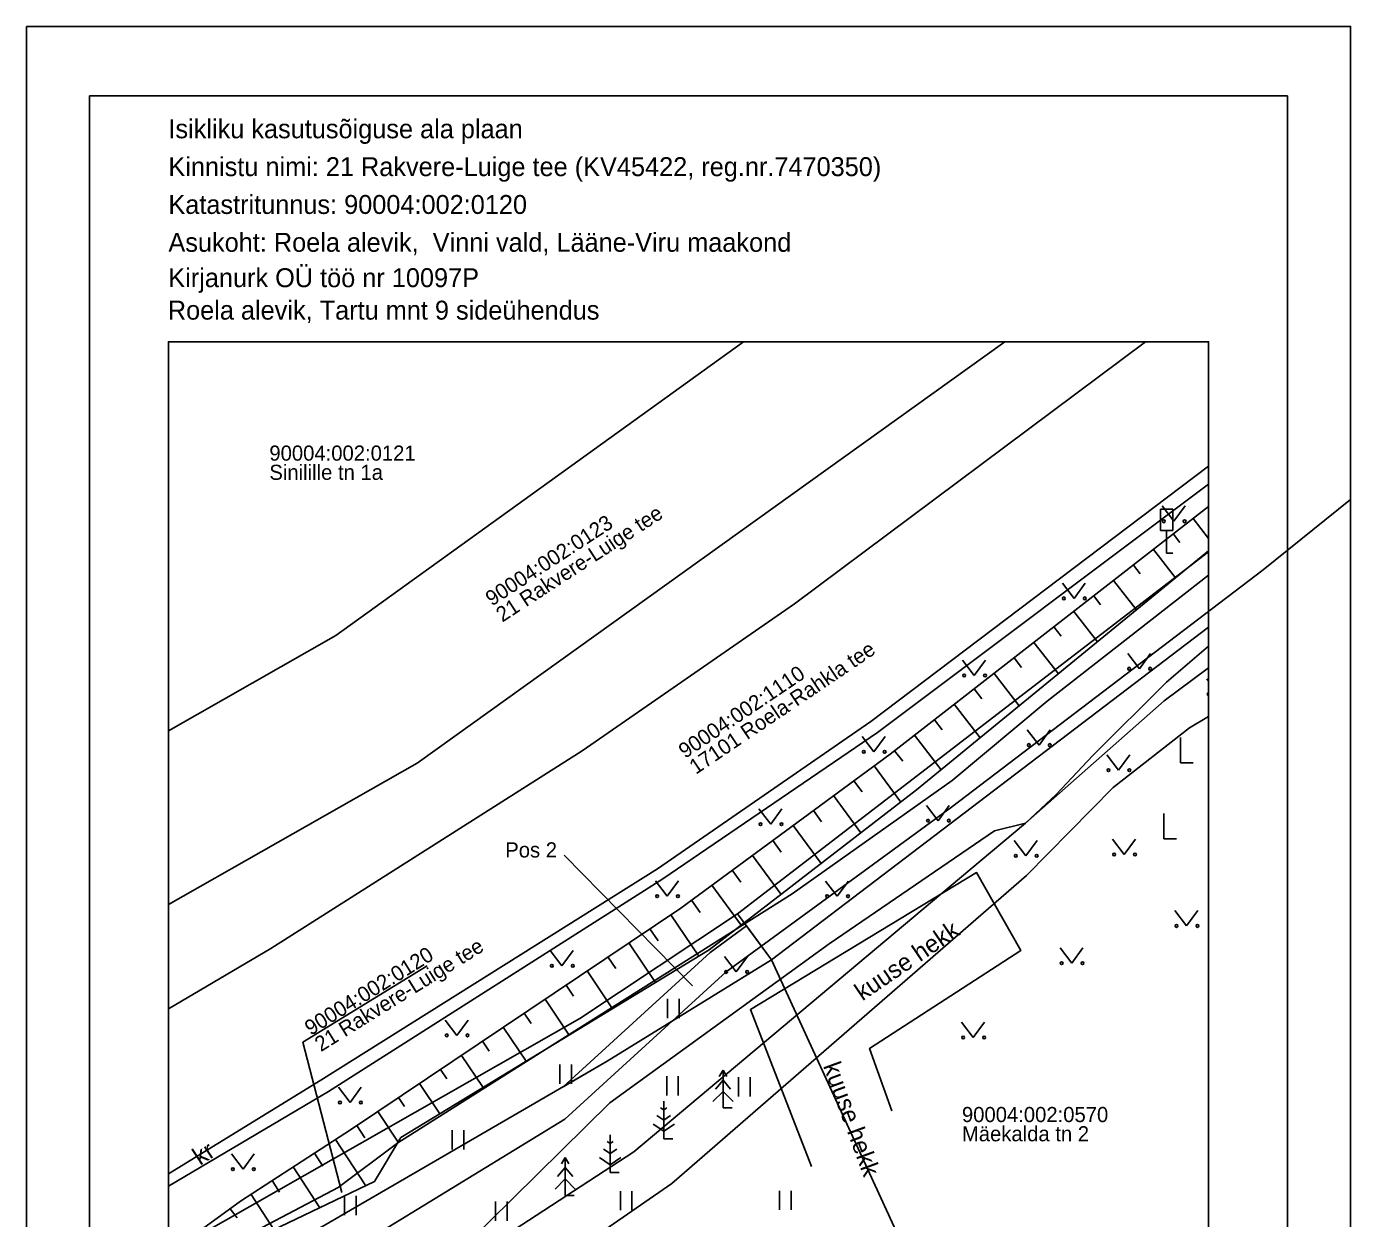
# Model space of a CAD drawing. Extents: x 647901 to 648048, y 6561291 to 6561412.
# Drawn here: x 647995.6 to 648048.1, y 6561364.9 to 6561412.2 of the extents above; entities that cross this region are included whole.
import ezdxf

# ---------------------------------------------------------------- set-up
doc = ezdxf.new("R2010")
doc.units = 0
for name, color, linetype in [('HALJASTUS', 7, 'Continuous'), ('KASUTUSALA', 7, 'Continuous'), ('LIIKLUS', 7, 'Continuous'), ('PIIR', 7, 'Continuous'), ('PR_SIDE', 7, 'Continuous'), ('PUU', 7, 'Continuous'), ('RELJEEF', 7, 'Continuous'), ('SITRASS', 7, 'Continuous'), ('TEE', 7, 'Continuous'), ('VORMISTUS_1', 7, 'Continuous')]:
    doc.layers.add(name, color=color, linetype=linetype)

msp = doc.modelspace()

# ---------------------------------------------------------------- linework, layer by layer
at = {"layer": 'HALJASTUS'}
for p, q in [((648040.646, 6561393.157), (648041.11, 6561392.55)), ((648041.11, 6561392.55), (648041.555, 6561393.157)), ((648036.689, 6561390.101), (648037.153, 6561389.494)), ((648037.153, 6561389.494), (648037.598, 6561390.101)), ((648032.732, 6561387.044), (648033.196, 6561386.438)), ((648033.196, 6561386.438), (648033.641, 6561387.044)), ((648039.279, 6561387.311), (648039.742, 6561386.705)), ((648039.742, 6561386.705), (648040.188, 6561387.311)), ((648042.423, 6561386.301), (648042.49, 6561386.213)), ((648028.752, 6561384.019), (648029.215, 6561383.412)), ((648029.215, 6561383.412), (648029.661, 6561384.019)), ((648035.299, 6561384.285), (648035.763, 6561383.679)), ((648035.763, 6561383.679), (648036.208, 6561384.285)), ((648041.376, 6561383.971), (648041.376, 6561382.971)), ((648038.454, 6561383.287), (648038.918, 6561382.68)), ((648038.918, 6561382.68), (648039.363, 6561383.287)), ((648041.376, 6561382.971), (648041.876, 6561382.971)), ((648031.298, 6561381.287), (648031.762, 6561380.68)), ((648031.762, 6561380.68), (648032.207, 6561381.287)), ((648024.66, 6561381.145), (648025.124, 6561380.539)), ((648025.124, 6561380.539), (648025.569, 6561381.145)), ((648040.717, 6561380.958), (648040.717, 6561379.958)), ((648034.78, 6561379.896), (648035.243, 6561379.29)), ((648035.243, 6561379.29), (648035.689, 6561379.896)), ((648038.678, 6561379.944), (648039.142, 6561379.338)), ((648039.142, 6561379.338), (648039.587, 6561379.944)), ((648040.717, 6561379.958), (648041.217, 6561379.958)), ((648020.556, 6561378.29), (648021.02, 6561377.683)), ((648021.02, 6561377.683), (648021.465, 6561378.29)), ((648027.297, 6561378.288), (648027.761, 6561377.681)), ((648027.761, 6561377.681), (648028.206, 6561378.288)), ((648041.153, 6561377.112), (648041.616, 6561376.505)), ((648041.616, 6561376.505), (648042.062, 6561377.112)), ((648016.385, 6561375.533), (648016.849, 6561374.926)), ((648016.849, 6561374.926), (648017.294, 6561375.533)), ((648036.598, 6561375.636), (648037.062, 6561375.029)), ((648037.062, 6561375.029), (648037.507, 6561375.636)), ((648023.297, 6561375.289), (648023.76, 6561374.682)), ((648023.76, 6561374.682), (648024.205, 6561375.289)), ((648021.036, 6561373.613), (648021.036, 6561372.852)), ((648021.491, 6561373.613), (648021.491, 6561372.852)), ((648012.214, 6561372.776), (648012.678, 6561372.169)), ((648012.678, 6561372.169), (648013.123, 6561372.776)), ((648032.694, 6561372.691), (648033.157, 6561372.084)), ((648033.157, 6561372.084), (648033.603, 6561372.691)), ((648016.767, 6561371.009), (648016.767, 6561370.248)), ((648017.223, 6561371.009), (648017.223, 6561370.248)), ((648021.007, 6561370.547), (648021.007, 6561369.785)), ((648021.462, 6561370.547), (648021.462, 6561369.785)), ((648023.853, 6561370.504), (648023.853, 6561369.742)), ((648024.308, 6561370.504), (648024.308, 6561369.742)), ((648007.983, 6561370.112), (648008.446, 6561369.505)), ((648008.446, 6561369.505), (648008.892, 6561370.112)), ((648012.499, 6561368.406), (648012.499, 6561367.645)), ((648012.954, 6561368.406), (648012.954, 6561367.645)), ((648003.738, 6561367.47), (648004.201, 6561366.864)), ((648004.201, 6561366.864), (648004.647, 6561367.47)), ((648025.476, 6561366.005), (648025.476, 6561365.244)), ((648025.931, 6561366.005), (648025.931, 6561365.244)), ((648008.23, 6561365.802), (648008.23, 6561365.041)), ((648008.685, 6561365.802), (648008.685, 6561365.041)), ((648014.217, 6561365.576), (648014.217, 6561364.815)), ((648014.672, 6561365.576), (648014.672, 6561364.815)), ((648019.165, 6561365.995), (648019.165, 6561365.234)), ((648019.62, 6561365.995), (648019.62, 6561365.234))]:
    msp.add_line(p, q, dxfattribs=at)
msp.add_lwpolyline([(648026.747, 6561366.971), (648024.322, 6561373.193), (648033.287, 6561378.621), (648035.039, 6561375.527), (648029.048, 6561371.649), (648029.933, 6561369.17)], dxfattribs=at)
for centre in [(648040.709, 6561392.55), (648041.538, 6561392.55), (648036.752, 6561389.494), (648037.58, 6561389.494), (648032.795, 6561386.438), (648033.623, 6561386.438), (648039.341, 6561386.705), (648040.17, 6561386.705), (648028.814, 6561383.412), (648029.643, 6561383.412), (648035.362, 6561383.679), (648036.191, 6561383.679), (648038.516, 6561382.68), (648039.345, 6561382.68), (648031.361, 6561380.68), (648032.19, 6561380.68), (648024.723, 6561380.539), (648025.552, 6561380.539), (648034.842, 6561379.29), (648035.671, 6561379.29), (648038.741, 6561379.338), (648039.57, 6561379.338), (648020.619, 6561377.683), (648021.447, 6561377.683), (648027.36, 6561377.681), (648028.189, 6561377.681), (648041.215, 6561376.505), (648042.044, 6561376.505), (648016.448, 6561374.926), (648017.276, 6561374.926), (648036.661, 6561375.029), (648037.489, 6561375.029), (648023.359, 6561374.682), (648024.188, 6561374.682), (648012.277, 6561372.169), (648013.105, 6561372.169), (648032.756, 6561372.084), (648033.585, 6561372.084), (648008.045, 6561369.505), (648008.874, 6561369.505), (648003.8, 6561366.864), (648004.629, 6561366.864)]:
    msp.add_circle(centre, 0.055, dxfattribs=at)
msp.add_arc((648042.485, 6561385.694), 0.055, 84.6333, 275.3667, dxfattribs=at)
at = {"layer": 'KASUTUSALA'}
msp.add_lwpolyline([(648016.894, 6561370.128), (648022.724, 6561375.457), (648024.162, 6561376.509), (648025.15, 6561375.16), (648018.64, 6561371.14)], close=True, dxfattribs=at)
at = {"layer": 'LIIKLUS'}
for p, q in [((648040.575, 6561393.037), (648040.575, 6561392.187)), ((648041.075, 6561393.037), (648040.575, 6561393.037)), ((648041.075, 6561393.037), (648041.075, 6561392.187)), ((648041.075, 6561392.187), (648040.575, 6561392.187)), ((648040.825, 6561392.187), (648040.825, 6561391.287)), ((648041.075, 6561391.287), (648040.825, 6561391.287))]:
    msp.add_line(p, q, dxfattribs=at)
at = {"layer": 'PIIR'}
for points in [[(648001.24, 6561384.247), (648007.88, 6561388.02), (648024.045, 6561399.668)], [(648024.045, 6561399.668), (648007.88, 6561388.02), (648001.24, 6561384.247)], [(648001.24, 6561377.35), (648011.11, 6561382.96), (648034.41, 6561399.668)], [(648034.41, 6561399.668), (648011.11, 6561382.96), (648001.24, 6561377.35)], [(648042.49, 6561391.337), (648023.81, 6561376.99), (648017.56, 6561372.83), (648001.24, 6561363.546)], [(648038.018, 6561347.168), (648025.15, 6561375.16), (648042.49, 6561388.346)], [(648001.24, 6561363.546), (648017.56, 6561372.83), (648023.81, 6561376.99), (648025.15, 6561375.16), (648018.64, 6561371.14), (648001.24, 6561361.053)], [(648001.24, 6561361.053), (648018.64, 6561371.14), (648025.15, 6561375.16), (648038.018, 6561347.168)], [(648011.5, 6561374.931), (648006.577, 6561371.897), (648008.122, 6561365.939)]]:
    msp.add_lwpolyline(points, dxfattribs=at)
at = {"layer": 'PR_SIDE'}
msp.add_lwpolyline([(648048.115, 6561393.411), (648044.656, 6561390.621), (648032.291, 6561381.218), (648023.359, 6561374.682), (648016.966, 6561368.839), (647995.615, 6561355.782)], dxfattribs=at)
at = {"layer": 'PUU'}
for p, q in [((648023.235, 6561370.791), (648023.085, 6561370.541)), ((648023.385, 6561370.541), (648023.235, 6561370.791)), ((648023.235, 6561370.791), (648023.235, 6561369.291)), ((648023.235, 6561370.391), (648022.935, 6561370.041)), ((648023.535, 6561370.041), (648023.235, 6561370.391)), ((648023.235, 6561369.941), (648022.835, 6561369.541)), ((648023.635, 6561369.541), (648023.235, 6561369.941)), ((648020.882, 6561369.212), (648020.758, 6561369.295)), ((648020.882, 6561369.562), (648020.882, 6561368.062)), ((648021.007, 6561369.295), (648020.882, 6561369.212)), ((648023.595, 6561369.291), (648023.235, 6561369.291)), ((648020.458, 6561368.652), (648020.882, 6561368.369)), ((648020.882, 6561368.812), (648020.615, 6561368.99)), ((648021.149, 6561368.99), (648020.882, 6561368.812)), ((648020.882, 6561368.369), (648021.306, 6561368.652)), ((648018.76, 6561368.23), (648018.76, 6561366.73)), ((648018.76, 6561367.48), (648018.493, 6561367.658)), ((648018.76, 6561367.88), (648018.635, 6561367.963)), ((648018.884, 6561367.963), (648018.76, 6561367.88)), ((648019.026, 6561367.658), (648018.76, 6561367.48)), ((648021.242, 6561368.062), (648020.882, 6561368.062)), ((648016.975, 6561367.325), (648016.825, 6561367.075)), ((648017.125, 6561367.075), (648016.975, 6561367.325)), ((648016.975, 6561367.325), (648016.975, 6561365.825)), ((648018.335, 6561367.319), (648018.76, 6561367.037)), ((648018.76, 6561367.037), (648019.184, 6561367.319)), ((648016.975, 6561366.925), (648016.675, 6561366.575)), ((648017.275, 6561366.575), (648016.975, 6561366.925)), ((648019.12, 6561366.73), (648018.76, 6561366.73)), ((648016.975, 6561366.475), (648016.575, 6561366.075)), ((648017.375, 6561366.075), (648016.975, 6561366.475)), ((648017.335, 6561365.825), (648016.975, 6561365.825))]:
    msp.add_line(p, q, dxfattribs=at)
at = {"layer": 'RELJEEF'}
for p, q in [((648041.88, 6561392.656), (648042.49, 6561391.87)), ((648041.09, 6561392.042), (648041.348, 6561391.711)), ((648040.301, 6561391.429), (648041.174, 6561390.304)), ((648039.511, 6561390.815), (648039.778, 6561390.472)), ((648038.721, 6561390.202), (648039.626, 6561389.037)), ((648037.931, 6561389.589), (648038.208, 6561389.233)), ((648037.142, 6561388.975), (648038.078, 6561387.769)), ((648036.352, 6561388.362), (648036.638, 6561387.994)), ((648035.562, 6561387.748), (648036.531, 6561386.501)), ((648034.772, 6561387.135), (648035.068, 6561386.755)), ((648033.983, 6561386.521), (648034.983, 6561385.233)), ((648033.193, 6561385.908), (648033.498, 6561385.515)), ((648032.403, 6561385.295), (648033.435, 6561383.965)), ((648031.613, 6561384.681), (648031.928, 6561384.276)), ((648030.824, 6561384.068), (648031.888, 6561382.698)), ((648030.034, 6561383.454), (648030.358, 6561383.037)), ((648029.232, 6561382.857), (648030.289, 6561381.418)), ((648028.426, 6561382.265), (648028.747, 6561381.828)), ((648027.62, 6561381.673), (648028.705, 6561380.197)), ((648026.815, 6561381.08), (648027.144, 6561380.632)), ((648026.009, 6561380.488), (648027.121, 6561378.976)), ((648025.203, 6561379.896), (648025.541, 6561379.436)), ((648024.398, 6561379.303), (648025.536, 6561377.754)), ((648023.592, 6561378.711), (648023.938, 6561378.241)), ((648022.786, 6561378.118), (648023.952, 6561376.533)), ((648021.98, 6561377.526), (648022.334, 6561377.045)), ((648021.163, 6561376.95), (648022.269, 6561375.303)), ((648020.333, 6561376.393), (648020.657, 6561375.91)), ((648019.503, 6561375.835), (648020.559, 6561374.262)), ((648018.673, 6561375.278), (648018.982, 6561374.817)), ((648017.842, 6561374.72), (648018.849, 6561373.221)), ((648017.012, 6561374.163), (648017.307, 6561373.724)), ((648016.182, 6561373.605), (648017.139, 6561372.18)), ((648015.352, 6561373.048), (648015.631, 6561372.632)), ((648014.522, 6561372.49), (648015.429, 6561371.14)), ((648013.692, 6561371.933), (648013.956, 6561371.539)), ((648012.861, 6561371.375), (648013.719, 6561370.099)), ((648012.031, 6561370.818), (648012.281, 6561370.446)), ((648011.201, 6561370.26), (648012.009, 6561369.058)), ((648010.371, 6561369.703), (648010.606, 6561369.353)), ((648009.541, 6561369.145), (648010.354, 6561367.934)), ((648008.71, 6561368.588), (648009.033, 6561368.108)), ((648007.874, 6561368.04), (648009.065, 6561366.205)), ((648007.035, 6561367.496), (648007.371, 6561366.978)), ((648006.196, 6561366.951), (648007.245, 6561365.335)), ((648005.358, 6561366.407), (648005.651, 6561365.955)), ((648004.519, 6561365.862), (648005.425, 6561364.466)), ((648003.696, 6561365.295), (648003.964, 6561364.927))]:
    msp.add_line(p, q, dxfattribs=at)
for points in [[(648001.24, 6561363.558), (648002.305, 6561364.281), (648004.107, 6561365.595), (648008.5, 6561368.446), (648021.556, 6561377.214), (648029.86, 6561383.32), (648042.49, 6561393.13)], [(648004.109, 6561363.838), (648009.418, 6561366.373), (648010.464, 6561368.118), (648022.685, 6561375.556), (648030.912, 6561381.898), (648042.49, 6561391.383)]]:
    msp.add_lwpolyline(points, dxfattribs=at)
at = {"layer": 'SITRASS'}
for points in [[(648042.49, 6561390.42), (648036.083, 6561385.412), (648032.317, 6561382.279), (648025.979, 6561377.774), (648016.987, 6561372.115), (648010.343, 6561367.908), (648007.97, 6561366.141), (648004.236, 6561364.166), (648001.24, 6561362.194)], [(648042.49, 6561387.595), (648040.817, 6561386.172), (648037.897, 6561383.269), (648036.442, 6561381.714), (648035.232, 6561380.578), (648033.02, 6561378.726), (648019.695, 6561367.554), (648011.084, 6561361.936)], [(648042.49, 6561386.736), (648040.723, 6561385.425), (648035.232, 6561380.578), (648033.992, 6561380.271), (648027.443, 6561375.801), (648018.744, 6561369.492), (648011.084, 6561361.936), (648001.24, 6561355.641)], [(648001.24, 6561351.944), (648002.379, 6561352.848), (648012.029, 6561359.913), (648014.644, 6561361.756), (648021.2, 6561366.3), (648035.273, 6561378.512), (648038.702, 6561381.989), (648041.726, 6561384.362), (648042.49, 6561384.811)]]:
    msp.add_lwpolyline(points, dxfattribs=at)
at = {"layer": 'TEE'}
for points in [[(648039.989, 6561399.668), (648026.062, 6561389.277), (648017.651, 6561383.446), (648005.304, 6561375.611), (648001.24, 6561373.226)], [(648001.24, 6561366.677), (648007.29, 6561370.386), (648020.637, 6561378.767), (648029.099, 6561384.606), (648042.49, 6561394.731)], [(648001.24, 6561366.188), (648007.59, 6561369.939), (648020.85, 6561378.37), (648029.362, 6561384.182), (648042.49, 6561394.018)]]:
    msp.add_lwpolyline(points, dxfattribs=at)
at = {"layer": 'VORMISTUS_1'}
msp.add_line((648022.021, 6561374.134), (648016.929, 6561379.31), dxfattribs=at)
for points in [[(647995.615, 6561412.168), (648048.115, 6561412.168), (648048.115, 6561337.918), (647995.615, 6561337.918)], [(647998.115, 6561340.668), (648045.615, 6561340.668), (648045.615, 6561409.418), (647998.115, 6561409.418)], [(647998.115, 6561409.418), (648045.615, 6561409.418), (648045.615, 6561340.668), (647998.115, 6561340.668)], [(648042.49, 6561347.168), (648001.24, 6561347.168), (648001.24, 6561399.668), (648042.49, 6561399.668)]]:
    msp.add_lwpolyline(points, close=True, dxfattribs=at)

# ---------------------------------------------------------------- texts
at = {"layer": 'HALJASTUS'}
for rotation, p in [(34.2255, (648028.76, 6561373.514)), (290.087, (648027.194, 6561370.961))]:
    msp.add_text('kuuse hekk', height=0.7, rotation=rotation, dxfattribs=at).set_placement(p)
at = {"layer": 'PIIR'}
for s, p in [('90004:002:0121', (648005.246, 6561394.954)), ('Sinilille tn 1a', (648005.246, 6561394.193)), ('90004:002:0570', (648032.708, 6561368.729)), ('Mäekalda tn 2', (648032.708, 6561367.967))]:
    msp.add_text(s, height=0.6, dxfattribs=at).set_placement(p)
for s, rotation, p in [('21 Rakvere-Luige tee', 33.1211, (648014.484, 6561388.53)), ('90004:002:0123', 33.1211, (648014.068, 6561389.168)), ('17101 Roela-Rahkla tee', 34.0008, (648022.157, 6561382.495)), ('90004:002:1110', 34.0008, (648021.731, 6561383.127)), ('90004:002:0120', 31.8574, (648006.886, 6561372.145)), ('21 Rakvere-Luige tee', 31.8574, (648007.288, 6561371.499))]:
    msp.add_text(s, height=0.6, rotation=rotation, dxfattribs=at).set_placement(p)
at = {"layer": 'TEE'}
msp.add_text('kr', height=0.7, rotation=33.3449, dxfattribs=at).set_placement((648002.498, 6561366.991))
at = {"layer": 'VORMISTUS_1'}
for s, p in [('Isikliku kasutusõiguse ala plaan', (648001.243, 6561407.736)), ('Kinnistu nimi: 21 Rakvere-Luige tee (KV45422, reg.nr.7470350)', (648001.243, 6561406.236)), ('Katastritunnus: 90004:002:0120', (648001.243, 6561404.736)), ('Asukoht: Roela alevik,  Vinni vald, Lääne-Viru maakond', (648001.243, 6561403.236)), ('Kirjanurk OÜ töö nr 10097P', (648001.239, 6561401.833)), ('Roela alevik, Tartu mnt 9 sideühendus', (648001.22, 6561400.546))]:
    msp.add_text(s, height=0.75, rotation=360, dxfattribs=at).set_placement(p)
msp.add_text('Pos 2', height=0.6, dxfattribs=at).set_placement((648014.599, 6561379.221))

doc.saveas('drawing.dxf')
